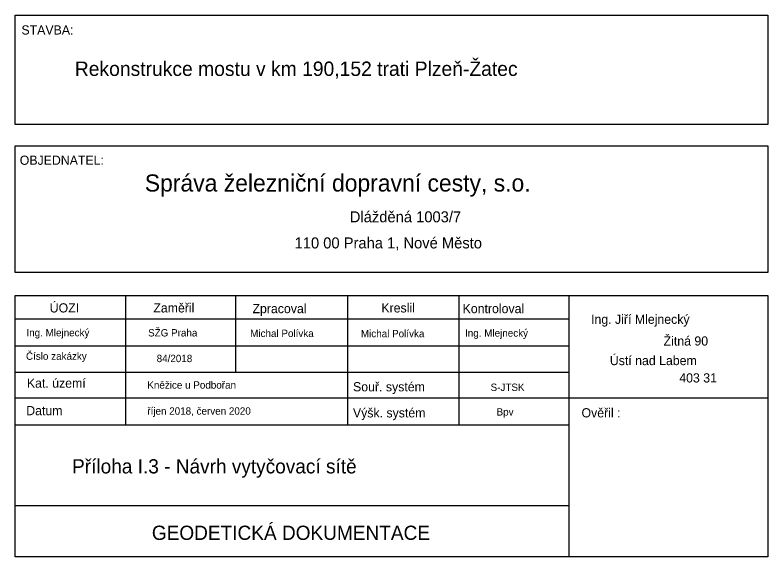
# Model space of a CAD drawing. Extents: x -879530 to -879371, y -1019242 to -1019127.
import ezdxf

# ---------------------------------------------------------------- set-up
doc = ezdxf.new("R2010")
doc.units = 0
doc.layers.add('LEGENDA', color=7, linetype='Continuous')
doc.layers.add('tabulka', color=7, linetype='Continuous')

msp = doc.modelspace()

# ---------------------------------------------------------------- linework, layer by layer
at = {"layer": 'tabulka'}
for p, q in [((-879530.09, -1019186.45), (-879371.44, -1019186.45)), ((-879506.8, -1019186.45), (-879506.8, -1019213.77)), ((-879483.66, -1019186.45), (-879483.66, -1019202.65)), ((-879460.06, -1019186.45), (-879460.06, -1019213.77)), ((-879436.61, -1019186.45), (-879436.61, -1019213.77)), ((-879413.31, -1019241.58), (-879413.31, -1019186.45)), ((-879530.09, -1019191.36), (-879413.31, -1019191.36)), ((-879530.09, -1019197.07), (-879413.31, -1019197.07)), ((-879530.09, -1019202.65), (-879413.31, -1019202.65)), ((-879530.09, -1019208.07), (-879371.44, -1019208.07)), ((-879530.09, -1019213.77), (-879413.31, -1019213.77)), ((-879530.09, -1019230.76), (-879413.31, -1019230.76))]:
    msp.add_line(p, q, dxfattribs=at)
for points in [[(-879530.09, -1019127.36), (-879371.44, -1019127.36), (-879371.44, -1019150.43), (-879530.09, -1019150.43)], [(-879530.09, -1019154.95), (-879371.44, -1019154.95), (-879371.44, -1019181.64), (-879530.09, -1019181.64)]]:
    msp.add_lwpolyline(points, close=True, dxfattribs=at)
msp.add_lwpolyline([(-879371.44, -1019186.45), (-879371.44, -1019241.58), (-879530.09, -1019241.58), (-879530.09, -1019186.45)], dxfattribs=at)

# ---------------------------------------------------------------- texts
at = {"layer": 'LEGENDA'}
msp.add_text('Rekonstrukce mostu v km 190,152 trati Plzeň-Žatec', height=3.04, dxfattribs=at).set_placement((-879517.5, -1019140.2))
at = {"layer": 'tabulka'}
for s, height, p in [('STAVBA:', 1.94, (-879528.75, -1019131.47)), ('OBJEDNATEL:', 1.94, (-879529.1, -1019158.93)), ('Správa železniční dopravní cesty, s.o.', 3.61, (-879502.75, -1019164.56)), ('Dlážděná 1003/7', 2.32, (-879459.55, -1019171.05)), ('110 00 Praha 1, Nové Město', 2.32, (-879471.19, -1019176.55)), ('ÚOZI', 1.94, (-879522.79, -1019190.05)), ('Zaměřil', 1.94, (-879500.95, -1019190.05)), ('Zpracoval', 1.94, (-879480.06, -1019190.2)), ('Kreslil', 1.94, (-879452.9, -1019190.05)), ('Kontroloval', 1.94, (-879435.78, -1019190.2)), ('Ing. Jiří Mlejnecký', 1.94, (-879408.71, -1019192.45)), ('Ing. Mlejnecký', 1.552, (-879527.69, -1019195.08)), ('SŽG Praha', 1.552, (-879502.06, -1019195.11)), ('Michal Polívka', 1.552, (-879480.54, -1019195.23)), ('Michal Polívka', 1.552, (-879457.21, -1019195.27)), ('Ing. Mlejnecký', 1.552, (-879435.26, -1019195.15)), ('Žitná 90', 1.94, (-879393.42, -1019197.03)), ('Číslo zakázky', 1.552, (-879527.79, -1019200.03)), ('84/2018', 1.552, (-879500.25, -1019200.52)), ('Ústí nad Labem', 1.94, (-879404.75, -1019201.15)), ('403 31', 1.94, (-879390.12, -1019204.81)), ('Kat. území', 1.94, (-879527.6, -1019205.91)), ('Kněžice u Podbořan', 1.552, (-879502.22, -1019206.11)), ('Souř. systém', 1.94, (-879458.87, -1019206.68)), ('S-JTSK', 1.552, (-879429.88, -1019206.59)), ('Datum', 1.94, (-879527.74, -1019211.71)), ('říjen 2018, červen 2020', 1.552, (-879502.22, -1019211.6)), ('Výšk. systém', 1.94, (-879458.89, -1019212.17)), ('Bpv', 1.552, (-879428.62, -1019211.78)), ('Ověřil :', 1.94, (-879410.72, -1019212.17)), ('Příloha I.3 - Návrh vytyčovací sítě', 3, (-879518.08, -1019223.98)), ('GEODETICKÁ DOKUMENTACE ', 3, (-879501.27, -1019237.99))]:
    msp.add_text(s, height=height, dxfattribs=at).set_placement(p)

doc.saveas('drawing.dxf')
